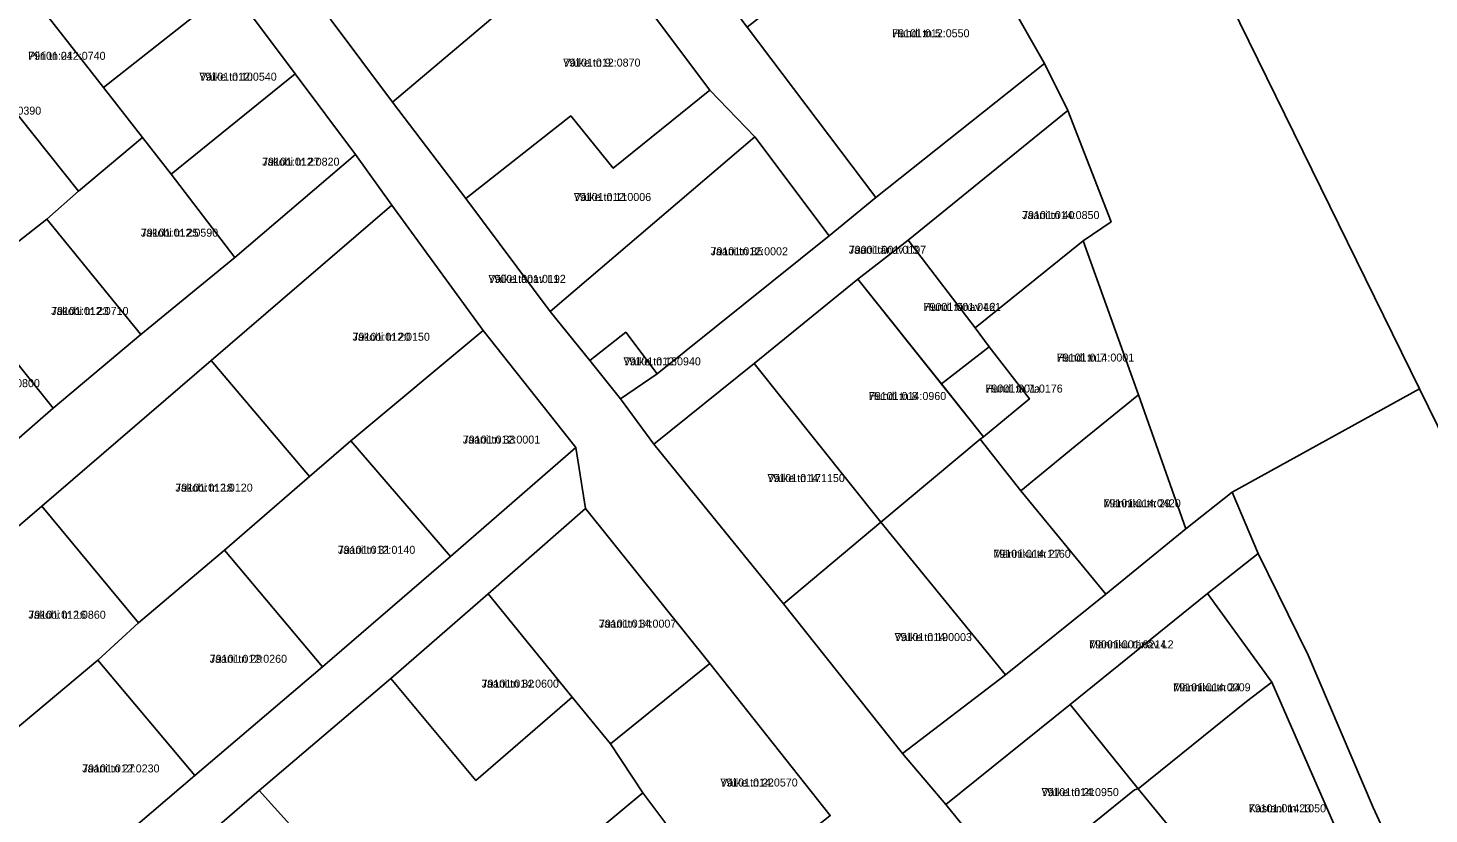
# Model space of a CAD drawing. Extents: x 587616 to 632239, y 6547421 to 6574977.
# Drawn here: x 612602.3 to 612864.9, y 6570843.8 to 6570991.1 of the extents above; entities that cross this region are included whole.
import ezdxf

# ---------------------------------------------------------------- set-up
doc = ezdxf.new("R2010")
doc.units = 0
for name, color, linetype in [('L_AADRESS', 7, 'Continuous'), ('PIIR', 7, 'Continuous'), ('TUNNUS', 7, 'Continuous')]:
    doc.layers.add(name, color=color, linetype=linetype)

msp = doc.modelspace()

# ---------------------------------------------------------------- linework, layer by layer
at = {"layer": 'PIIR'}
for points in [[(612726.89, 6571165.86), (612767.17, 6571119.09), (612863.16, 6570923.48), (612828.02, 6570904.09), (612819.34, 6570897.21), (612810.45, 6570922.36), (612800.08, 6570951.24), (612805.32, 6570954.81), (612797.24, 6570975.69), (612792.85, 6570984.48), (612772.89, 6571019.49), (612780.75, 6571025.66), (612767.41, 6571055.78), (612746.99, 6571085.5), (612741.08, 6571091.35), (612719.21, 6571117.73), (612693.74, 6571147.16), (612710.27, 6571182.39)], [(612686.59, 6571037.51), (612696.52, 6571045.11), (612717.81, 6571016.8), (612737.1, 6570991.29), (612761.24, 6570959.34), (612752.48, 6570952.17), (612738.54, 6570970.73), (612730.07, 6570979.46), (612708.25, 6571008.63)], [(612708.25, 6571008.63), (612699, 6571001.3), (612670.59, 6570977.27), (612647.6, 6571008.08), (612677.38, 6571030.47), (612684.24, 6571035.72), (612686.59, 6571037.51)], [(612772.89, 6571019.49), (612792.85, 6570984.48), (612761.24, 6570959.34), (612737.1, 6570991.29)], [(612616.39, 6570979.98), (612604.88, 6570994.7), (612628.28, 6571015.06), (612640.19, 6570998.83)], [(612593.08, 6571009.5), (612604.88, 6570994.7), (612616.39, 6570979.98), (612623.73, 6570970.6), (612611.71, 6570960.58), (612580.84, 6570999.28)], [(612699, 6571001.3), (612708.25, 6571008.63), (612730.07, 6570979.46), (612711.97, 6570964.84), (612704.03, 6570974.67), (612684.37, 6570959.19), (612670.59, 6570977.27)], [(612580.84, 6570999.28), (612611.71, 6570960.58), (612605.79, 6570955.33), (612599.68, 6570950.51), (612568.76, 6570989.08)], [(612623.73, 6570970.6), (612616.39, 6570979.98), (612640.19, 6570998.83), (612652.35, 6570982.57), (612629.09, 6570963.71)], [(612629.09, 6570963.71), (612652.35, 6570982.57), (612663.66, 6570967.42), (612641.02, 6570948.09)], [(612713.35, 6570921.64), (612720.2, 6570926.33), (612752.48, 6570952.17), (612761.24, 6570959.34), (612792.85, 6570984.48), (612797.24, 6570975.69), (612767.27, 6570951.36), (612757.86, 6570944.03), (612738.41, 6570928.25), (612719.62, 6570913.14)], [(612700.15, 6570937.97), (612684.37, 6570959.19), (612704.03, 6570974.67), (612711.97, 6570964.84), (612730.07, 6570979.46), (612738.54, 6570970.73)], [(612779.85, 6570934.95), (612767.27, 6570951.36), (612797.24, 6570975.69), (612805.32, 6570954.81), (612800.08, 6570951.24)], [(612605.79, 6570955.33), (612611.71, 6570960.58), (612623.73, 6570970.6), (612629.09, 6570963.71), (612641.02, 6570948.09), (612623.43, 6570933.68)], [(612738.54, 6570970.73), (612752.48, 6570952.17), (612720.2, 6570926.33), (612714.33, 6570934.09), (612707.6, 6570928.83), (612700.15, 6570937.97)], [(612655.02, 6570907.07), (612636.6, 6570928.83), (612670.45, 6570957.92), (612687.62, 6570934.4), (612662.76, 6570913.72)], [(612599.68, 6570950.51), (612605.79, 6570955.33), (612623.43, 6570933.68), (612606.95, 6570919.88), (612589.74, 6570941.27)], [(612773.51, 6570924.43), (612757.86, 6570944.03), (612767.27, 6570951.36), (612779.85, 6570934.95), (612782.48, 6570931.38)], [(612788.43, 6570904.36), (612780.8, 6570914.08), (612781.42, 6570914.49), (612790, 6570921.61), (612782.48, 6570931.38), (612779.85, 6570934.95), (612800.08, 6570951.24), (612810.45, 6570922.36), (612798.57, 6570912.76)], [(612757.86, 6570944.03), (612781.42, 6570914.49), (612780.8, 6570914.08), (612762.18, 6570898.48), (612738.41, 6570928.25)], [(612582.22, 6570916.21), (612573.01, 6570927.38), (612575.82, 6570929.61), (612587.53, 6570939.73), (612589.74, 6570941.27), (612606.95, 6570919.88), (612590.75, 6570905.76), (612587.73, 6570909.16)], [(612687.62, 6570934.4), (612704.96, 6570912.48), (612681.48, 6570892.04), (612662.76, 6570913.72)], [(612714.33, 6570934.09), (612720.2, 6570926.33), (612713.35, 6570921.64), (612707.6, 6570928.83)], [(612773.51, 6570924.43), (612782.48, 6570931.38), (612790, 6570921.61), (612781.42, 6570914.49)], [(612639.09, 6570893.26), (612622.96, 6570879.59), (612604.85, 6570901.47), (612636.6, 6570928.83), (612655.02, 6570907.07)], [(612738.41, 6570928.25), (612762.18, 6570898.48), (612743.92, 6570883.16), (612719.62, 6570913.14)], [(612804.31, 6570884.98), (612788.43, 6570904.36), (612798.57, 6570912.76), (612810.45, 6570922.36), (612819.34, 6570897.21)], [(613066.18, 6570509.76), (613054.62, 6570505.86), (613043.94, 6570497.56), (613034.17, 6570509.95), (612947.74, 6570616.12), (612980.87, 6570635.47), (612962.24, 6570682.13), (612937.04, 6570717.08), (612927.83, 6570730.24), (612911.9, 6570752.2), (612895.02, 6570775.56), (612878.91, 6570797.8), (612864.22, 6570817.95), (612864.31, 6570823.48), (612854.46, 6570844.99), (612842.27, 6570873.57), (612832.9, 6570892.6), (612828.02, 6570904.09), (612863.16, 6570923.48)], [(612639.09, 6570893.26), (612655.02, 6570907.07), (612662.76, 6570913.72), (612681.48, 6570892.04), (612657.49, 6570871.39)], [(612780.8, 6570914.08), (612788.43, 6570904.36), (612804.31, 6570884.98), (612785.53, 6570869.86), (612762.18, 6570898.48)], [(612828.02, 6570904.09), (612832.9, 6570892.6), (612823.42, 6570885.08), (612797.68, 6570864.31), (612774.37, 6570845.55), (612766.24, 6570855.11), (612785.53, 6570869.86), (612804.31, 6570884.98), (612819.34, 6570897.21)], [(612622.96, 6570879.59), (612615.37, 6570872.59), (612599.5, 6570859.29), (612581.45, 6570881.46), (612604.85, 6570901.47)], [(612706.77, 6570901.03), (612730.08, 6570872.01), (612711.46, 6570856.93), (612704.26, 6570865.65), (612688.52, 6570885.07)], [(612766.24, 6570855.11), (612743.92, 6570883.16), (612762.18, 6570898.48), (612785.53, 6570869.86)], [(612615.37, 6570872.59), (612622.96, 6570879.59), (612639.09, 6570893.26), (612657.49, 6570871.39), (612633.51, 6570850.98)], [(612812.13, 6570798.78), (612835.41, 6570817.7), (612851.81, 6570831.05), (612835.45, 6570868.48), (612823.42, 6570885.08), (612832.9, 6570892.6), (612842.27, 6570873.57), (612854.46, 6570844.99), (612864.31, 6570823.48), (612864.22, 6570817.95), (612819.28, 6570781.43)], [(612670.31, 6570869.17), (612688.52, 6570885.07), (612704.26, 6570865.65), (612686.24, 6570850.02)], [(612797.68, 6570864.31), (612823.42, 6570885.08), (612835.45, 6570868.48), (612830.73, 6570864.84), (612810.43, 6570848.46)], [(612609.62, 6570830.53), (612591.26, 6570852.2), (612599.5, 6570859.29), (612615.37, 6570872.59), (612633.51, 6570850.98)], [(612730.08, 6570872.01), (612752.66, 6570843.48), (612732.71, 6570827.46), (612717.54, 6570847.72), (612711.46, 6570856.93)], [(612645.61, 6570848.15), (612670.31, 6570869.17), (612686.24, 6570850.02), (612704.26, 6570865.65), (612711.46, 6570856.93), (612717.54, 6570847.72), (612698.74, 6570832.05), (612680.2, 6570816.82), (612676.67, 6570813.74)], [(612810.43, 6570848.46), (612830.73, 6570864.84), (612835.45, 6570868.48), (612851.81, 6570831.05), (612835.41, 6570817.7), (612822.94, 6570833.15)], [(612774.37, 6570845.55), (612797.68, 6570864.31), (612810.43, 6570848.46), (612809.69, 6570848.31), (612787.05, 6570829.93)], [(612645.61, 6570848.15), (612676.67, 6570813.74), (612661.71, 6570801.23), (612651.56, 6570793.24), (612622.48, 6570828.15)], [(612698.74, 6570832.05), (612717.54, 6570847.72), (612732.71, 6570827.46), (612714.26, 6570813.31)], [(612787.05, 6570829.93), (612809.69, 6570848.31), (612810.43, 6570848.46), (612822.94, 6570833.15), (612799.62, 6570814.38)]]:
    msp.add_lwpolyline(points, close=True, dxfattribs=at)
for points in [[(613066.18, 6570509.76), (612863.16, 6570923.48), (612767.17, 6571119.09)], [(612647.6, 6571008.08), (612670.59, 6570977.27), (612684.37, 6570959.19), (612700.15, 6570937.97), (612707.6, 6570928.83), (612713.35, 6570921.64), (612719.62, 6570913.14), (612743.92, 6570883.16), (612766.24, 6570855.11), (612774.37, 6570845.55), (612787.05, 6570829.93)], [(612752.66, 6570843.48), (612730.08, 6570872.01), (612706.77, 6570901.03), (612704.96, 6570912.48), (612687.62, 6570934.4), (612670.45, 6570957.92), (612663.66, 6570967.42), (612652.35, 6570982.57), (612640.19, 6570998.83)], [(612590.75, 6570905.76), (612606.95, 6570919.88), (612623.43, 6570933.68), (612641.02, 6570948.09), (612663.66, 6570967.42), (612670.45, 6570957.92), (612636.6, 6570928.83), (612604.85, 6570901.47), (612581.45, 6570881.46)], [(612586.07, 6570810.2), (612609.62, 6570830.53), (612633.51, 6570850.98), (612657.49, 6570871.39), (612681.48, 6570892.04), (612704.96, 6570912.48), (612706.77, 6570901.03), (612688.52, 6570885.07), (612670.31, 6570869.17), (612645.61, 6570848.15), (612622.48, 6570828.15), (612606.95, 6570814.75), (612587.65, 6570798.13)]]:
    msp.add_lwpolyline(points, dxfattribs=at)

# ---------------------------------------------------------------- texts
at = {"layer": 'L_AADRESS'}
for s, p in [('Hundi tn 5', (612764.28, 6570989.41)), ('Piiri tn 24', (612602.29, 6570985.18)), ('Väike tn 9', (612702.59, 6570983.91)), ('Väike tn 10', (612634.38, 6570981.27)), ('Jakobi tn 27', (612646.15, 6570965.33)), ('Väike tn 11', (612704.59, 6570958.71)), ('Jaani tn 40', (612788.64, 6570955.32)), ('Jakobi tn 25', (612623.41, 6570952.02)), ('Jaani tn 35', (612730.23, 6570948.53)), ('Jaani tänav L3', (612756.14, 6570948.81)), ('Väike tänav L1', (612688.58, 6570943.36)), ('Jakobi tn 23', (612606.59, 6570937.34)), ('Hundi tänav L2', (612770.17, 6570938.1)), ('Jakobi tn 20', (612663.1, 6570932.5)), ('Hundi tn 7', (612795.15, 6570928.6)), ('Väike tn 13', (612713.9, 6570927.89)), ('Hundi tn 8', (612759.91, 6570921.39)), ('Hundi tn 7a', (612781.75, 6570922.79)), ('Jaani tn 33', (612683.78, 6570913.22)), ('Väike tn 17', (612740.9, 6570906.01)), ('Jakobi tn 18', (612629.88, 6570904.21)), ('Männiku tn 29', (612803.89, 6570901.28)), ('Jaani tn 31', (612660.36, 6570892.55)), ('Männiku tn 27', (612783.25, 6570891.81)), ('Jakobi tn 16', (612602.32, 6570880.38)), ('Jaani tn 34', (612709.3, 6570878.71)), ('Väike tn 19', (612764.73, 6570876.19)), ('Männiku tänav L2', (612801.2, 6570874.82)), ('Jaani tn 29', (612636.32, 6570872.12)), ('Jaani tn 32', (612687.29, 6570867.46)), ('Männiku tn 24', (612816.98, 6570866.77)), ('Jaani tn 27', (612612.41, 6570851.56)), ('Väike tn 22', (612732.06, 6570848.92)), ('Väike tn 21', (612792.27, 6570847.12)), ('Kastani tn 23', (612831.12, 6570844.08))]:
    msp.add_text(s, height=1.5, dxfattribs=at).set_placement(p)
at = {"layer": 'TUNNUS'}
for s, p in [('79101:012:0550', (612764.28, 6570989.41)), ('79101:012:0740', (612602.29, 6570985.18)), ('79101:012:0870', (612702.59, 6570983.91)), ('79101:012:0540', (612634.38, 6570981.27)), ('79101:012:0390', (612590.23, 6570974.9)), ('79101:012:0820', (612646.15, 6570965.33)), ('79101:012:0006', (612704.59, 6570958.71)), ('79101:014:0850', (612788.64, 6570955.32)), ('79101:012:0590', (612623.41, 6570952.02)), ('79101:012:0002', (612730.23, 6570948.53)), ('79001:001:0197', (612756.14, 6570948.81)), ('79001:001:0192', (612688.58, 6570943.36)), ('79101:012:0710', (612606.59, 6570937.34)), ('79001:001:0461', (612770.17, 6570938.1)), ('79101:012:0150', (612663.1, 6570932.5)), ('79101:014:0001', (612795.15, 6570928.6)), ('79101:012:0940', (612713.9, 6570927.89)), ('79101:012:0800', (612589.98, 6570923.8)), ('79101:014:0960', (612759.91, 6570921.39)), ('79001:001:0176', (612781.75, 6570922.79)), ('79101:012:0001', (612683.78, 6570913.22)), ('79101:014:1150', (612740.9, 6570906.01)), ('79101:012:0120', (612629.88, 6570904.21)), ('79101:014:0420', (612803.89, 6570901.28)), ('79101:012:0140', (612660.36, 6570892.55)), ('79101:014:1160', (612783.25, 6570891.81)), ('79101:012:0860', (612602.32, 6570880.38)), ('79101:014:0007', (612709.3, 6570878.71)), ('79101:014:0003', (612764.73, 6570876.19)), ('79001:001:0214', (612801.2, 6570874.82)), ('79101:012:0260', (612636.32, 6570872.12)), ('79101:014:0600', (612687.29, 6570867.46)), ('79101:014:0009', (612816.98, 6570866.77)), ('79101:012:0230', (612612.41, 6570851.56)), ('79101:014:0570', (612732.06, 6570848.92)), ('79101:014:0950', (612792.27, 6570847.12)), ('79101:014:1050', (612831.12, 6570844.08))]:
    msp.add_text(s, height=1.5, dxfattribs=at).set_placement(p)

doc.saveas('drawing.dxf')
